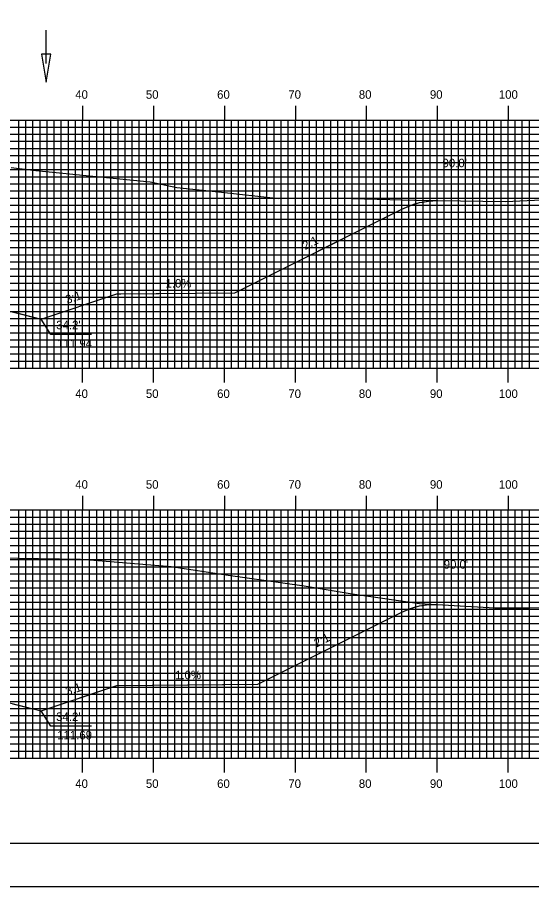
# Model space of a CAD drawing. Extents: x 1768087 to 1768430, y 442591 to 442811.
# Drawn here: x 1768283.8 to 1768356.3, y 442590.5 to 442713.1 of the extents above; entities that cross this region are included whole.
import ezdxf

# ---------------------------------------------------------------- set-up
doc = ezdxf.new("R2010")
doc.units = 0
for name, color, linetype in [('ANNOTATION', 7, 'Continuous'), ('BORDER', 7, 'Continuous'), ('D_Drainage_Ditch_Line', 7, 'Continuous'), ('D_Roadway_Centerline', 7, 'Continuous'), ('D_Roadway_SlopeLines', 7, 'Continuous'), ('D_Text_Standard', 7, 'Continuous'), ('H_V ANNOTATION', 7, 'Continuous'), ('MAJOR', 7, 'Continuous'), ('MINOR', 7, 'Continuous'), ('PLOT BOUNDARY', 7, 'Continuous'), ('S_Roadway_Centerline', 7, 'Continuous')]:
    doc.layers.add(name, color=color, linetype=linetype)

msp = doc.modelspace()

# ---------------------------------------------------------------- linework, layer by layer
at = {"layer": 'ANNOTATION'}
for points in [[(1768294.2, 442668.43), (1768288.51, 442668.43), (1768287.14, 442670.6)], [(1768294.2, 442613.18), (1768288.51, 442613.18), (1768287.14, 442615.35)]]:
    msp.add_lwpolyline(points, dxfattribs=at)
at = {"layer": 'BORDER'}
msp.add_lwpolyline([(1768103.36, 442596.67), (1768423.36, 442596.67), (1768423.36, 442806.67), (1768103.36, 442806.67)], close=True, dxfattribs=at)
at = {"layer": 'D_Drainage_Ditch_Line'}
msp.add_line((1768287.83, 442706.66), (1768287.82, 442711.36), dxfattribs=at)
msp.add_lwpolyline([(1768288.48, 442707.97), (1768287.17, 442707.97), (1768287.83, 442704.03)], close=True, dxfattribs=at)
at = {"layer": 'D_Roadway_Centerline'}
for points in [[(1768283.14, 442671.6), (1768287.14, 442670.6), (1768287.14, 442670.6), (1768297.77, 442674.15), (1768298.34, 442674.15), (1768314.4, 442674.31), (1768314.41, 442674.31), (1768321.65, 442677.93), (1768337.96, 442686.09), (1768338.98, 442686.53), (1768339.21, 442686.63), (1768339.67, 442686.78), (1768340.46, 442687.02), (1768340.87, 442687.09), (1768341.71, 442687.24), (1768342.96, 442687.3)], [(1768283.14, 442616.35), (1768287.13, 442615.35), (1768287.14, 442615.35), (1768291.48, 442616.8), (1768297.77, 442618.9), (1768312.95, 442619.05), (1768317.67, 442619.1), (1768317.67, 442619.1), (1768331.6, 442626.06), (1768337.96, 442629.24), (1768337.96, 442629.24), (1768339.21, 442629.78), (1768339.75, 442629.94), (1768340.46, 442630.14), (1768340.83, 442630.2), (1768341.71, 442630.33), (1768342.96, 442630.35)]]:
    msp.add_lwpolyline(points, dxfattribs=at)
at = {"layer": 'D_Roadway_SlopeLines'}
for points in [[(1768297.77, 442674.15), (1768314.41, 442674.31), (1768337.96, 442686.09), (1768339.21, 442686.63), (1768340.46, 442687.02), (1768341.71, 442687.24), (1768342.96, 442687.3)], [(1768272.96, 442674.15), (1768287.14, 442670.6)], [(1768287.14, 442670.6), (1768297.77, 442674.15)], [(1768297.77, 442618.9), (1768317.67, 442619.1), (1768337.96, 442629.24), (1768339.21, 442629.78), (1768340.46, 442630.14), (1768341.71, 442630.33), (1768342.96, 442630.35)], [(1768272.96, 442618.9), (1768287.14, 442615.35)], [(1768287.14, 442615.35), (1768297.77, 442618.9)]]:
    msp.add_lwpolyline(points, dxfattribs=at)
at = {"layer": 'MAJOR'}
for p, q in [((1768292.96, 442700.67), (1768292.96, 442698.67)), ((1768302.96, 442700.67), (1768302.96, 442698.67)), ((1768312.96, 442700.67), (1768312.96, 442698.67)), ((1768322.96, 442700.67), (1768322.96, 442698.67)), ((1768332.96, 442700.67), (1768332.96, 442698.67)), ((1768342.96, 442700.67), (1768342.96, 442698.67)), ((1768352.96, 442700.67), (1768352.96, 442698.67)), ((1768112.96, 442698.67), (1768392.96, 442698.67)), ((1768112.96, 442698.67), (1768392.96, 442698.67)), ((1768292.96, 442663.67), (1768292.96, 442698.67)), ((1768302.96, 442663.67), (1768302.96, 442698.67)), ((1768312.96, 442663.67), (1768312.96, 442698.67)), ((1768322.96, 442663.67), (1768322.96, 442698.67)), ((1768332.96, 442663.67), (1768332.96, 442698.67)), ((1768342.96, 442663.67), (1768342.96, 442698.67)), ((1768352.96, 442663.67), (1768352.96, 442698.67)), ((1768112.96, 442693.67), (1768392.96, 442693.67)), ((1768112.96, 442688.67), (1768392.96, 442688.67)), ((1768112.96, 442683.67), (1768392.96, 442683.67)), ((1768112.96, 442678.67), (1768392.96, 442678.67)), ((1768112.96, 442673.67), (1768392.96, 442673.67)), ((1768112.96, 442668.67), (1768392.96, 442668.67)), ((1768112.96, 442663.67), (1768392.96, 442663.67)), ((1768112.96, 442663.67), (1768392.96, 442663.67)), ((1768292.96, 442661.66), (1768292.96, 442663.67)), ((1768302.96, 442661.66), (1768302.96, 442663.67)), ((1768312.96, 442661.66), (1768312.96, 442663.67)), ((1768322.96, 442661.66), (1768322.96, 442663.67)), ((1768332.96, 442661.66), (1768332.96, 442663.67)), ((1768342.96, 442661.66), (1768342.96, 442663.67)), ((1768352.96, 442661.66), (1768352.96, 442663.67)), ((1768292.96, 442645.67), (1768292.96, 442643.67)), ((1768302.96, 442645.67), (1768302.96, 442643.67)), ((1768312.96, 442645.67), (1768312.96, 442643.67)), ((1768322.96, 442645.67), (1768322.96, 442643.67)), ((1768332.96, 442645.67), (1768332.96, 442643.67)), ((1768342.96, 442645.67), (1768342.96, 442643.67)), ((1768352.96, 442645.67), (1768352.96, 442643.67)), ((1768112.96, 442643.67), (1768392.96, 442643.67)), ((1768112.96, 442643.67), (1768392.96, 442643.67)), ((1768292.96, 442608.67), (1768292.96, 442643.67)), ((1768302.96, 442608.67), (1768302.96, 442643.67)), ((1768312.96, 442608.67), (1768312.96, 442643.67)), ((1768322.96, 442608.67), (1768322.96, 442643.67)), ((1768332.96, 442608.67), (1768332.96, 442643.67)), ((1768342.96, 442608.67), (1768342.96, 442643.67)), ((1768352.96, 442608.67), (1768352.96, 442643.67)), ((1768112.96, 442638.67), (1768392.96, 442638.67)), ((1768112.96, 442633.67), (1768392.96, 442633.67)), ((1768112.96, 442628.67), (1768392.96, 442628.67)), ((1768112.96, 442623.67), (1768392.96, 442623.67)), ((1768112.96, 442618.67), (1768392.96, 442618.67)), ((1768112.96, 442613.67), (1768392.96, 442613.67)), ((1768112.96, 442608.67), (1768392.96, 442608.67)), ((1768112.96, 442608.67), (1768392.96, 442608.67)), ((1768292.96, 442606.66), (1768292.96, 442608.67)), ((1768302.96, 442606.66), (1768302.96, 442608.67)), ((1768312.96, 442606.66), (1768312.96, 442608.67)), ((1768322.96, 442606.66), (1768322.96, 442608.67)), ((1768332.96, 442606.66), (1768332.96, 442608.67)), ((1768342.96, 442606.66), (1768342.96, 442608.67)), ((1768352.96, 442606.66), (1768352.96, 442608.67))]:
    msp.add_line(p, q, dxfattribs=at)
at = {"layer": 'MINOR'}
for p, q in [((1768283.96, 442663.67), (1768283.96, 442698.67)), ((1768284.96, 442663.67), (1768284.96, 442698.67)), ((1768285.96, 442663.67), (1768285.96, 442698.67)), ((1768286.96, 442663.67), (1768286.96, 442698.67)), ((1768287.96, 442663.67), (1768287.96, 442698.67)), ((1768288.96, 442663.67), (1768288.96, 442698.67)), ((1768289.96, 442663.67), (1768289.96, 442698.67)), ((1768290.96, 442663.67), (1768290.96, 442698.67)), ((1768291.96, 442663.67), (1768291.96, 442698.67)), ((1768293.96, 442663.67), (1768293.96, 442698.67)), ((1768294.96, 442663.67), (1768294.96, 442698.67)), ((1768295.96, 442663.67), (1768295.96, 442698.67)), ((1768296.96, 442663.67), (1768296.96, 442698.67)), ((1768297.96, 442663.67), (1768297.96, 442698.67)), ((1768298.96, 442663.67), (1768298.96, 442698.67)), ((1768299.96, 442663.67), (1768299.96, 442698.67)), ((1768300.96, 442663.67), (1768300.96, 442698.67)), ((1768301.96, 442663.67), (1768301.96, 442698.67)), ((1768303.96, 442663.67), (1768303.96, 442698.67)), ((1768304.96, 442663.67), (1768304.96, 442698.67)), ((1768305.96, 442663.67), (1768305.96, 442698.67)), ((1768306.96, 442663.67), (1768306.96, 442698.67)), ((1768307.96, 442663.67), (1768307.96, 442698.67)), ((1768308.96, 442663.67), (1768308.96, 442698.67)), ((1768309.96, 442663.67), (1768309.96, 442698.67)), ((1768310.96, 442663.67), (1768310.96, 442698.67)), ((1768311.96, 442663.67), (1768311.96, 442698.67)), ((1768313.96, 442663.67), (1768313.96, 442698.67)), ((1768314.96, 442663.67), (1768314.96, 442698.67)), ((1768315.96, 442663.67), (1768315.96, 442698.67)), ((1768316.96, 442663.67), (1768316.96, 442698.67)), ((1768317.96, 442663.67), (1768317.96, 442698.67)), ((1768318.96, 442663.67), (1768318.96, 442698.67)), ((1768319.96, 442663.67), (1768319.96, 442698.67)), ((1768320.96, 442663.67), (1768320.96, 442698.67)), ((1768321.96, 442663.67), (1768321.96, 442698.67)), ((1768323.96, 442663.67), (1768323.96, 442698.67)), ((1768324.96, 442663.67), (1768324.96, 442698.67)), ((1768325.96, 442663.67), (1768325.96, 442698.67)), ((1768326.96, 442663.67), (1768326.96, 442698.67)), ((1768327.96, 442663.67), (1768327.96, 442698.67)), ((1768328.96, 442663.67), (1768328.96, 442698.67)), ((1768329.96, 442663.67), (1768329.96, 442698.67)), ((1768330.96, 442663.67), (1768330.96, 442698.67)), ((1768331.96, 442663.67), (1768331.96, 442698.67)), ((1768333.96, 442663.67), (1768333.96, 442698.67)), ((1768334.96, 442663.67), (1768334.96, 442698.67)), ((1768335.96, 442663.67), (1768335.96, 442698.67)), ((1768336.96, 442663.67), (1768336.96, 442698.67)), ((1768337.96, 442663.67), (1768337.96, 442698.67)), ((1768338.96, 442663.67), (1768338.96, 442698.67)), ((1768339.96, 442663.67), (1768339.96, 442698.67)), ((1768340.96, 442663.67), (1768340.96, 442698.67)), ((1768341.96, 442663.67), (1768341.96, 442698.67)), ((1768343.96, 442663.67), (1768343.96, 442698.67)), ((1768344.96, 442663.67), (1768344.96, 442698.67)), ((1768345.96, 442663.67), (1768345.96, 442698.67)), ((1768346.96, 442663.67), (1768346.96, 442698.67)), ((1768347.96, 442663.67), (1768347.96, 442698.67)), ((1768348.96, 442663.67), (1768348.96, 442698.67)), ((1768349.96, 442663.67), (1768349.96, 442698.67)), ((1768350.96, 442663.67), (1768350.96, 442698.67)), ((1768351.96, 442663.67), (1768351.96, 442698.67)), ((1768353.96, 442663.67), (1768353.96, 442698.67)), ((1768354.96, 442663.67), (1768354.96, 442698.67)), ((1768355.96, 442663.67), (1768355.96, 442698.67)), ((1768112.96, 442697.67), (1768392.96, 442697.67)), ((1768112.96, 442696.67), (1768392.96, 442696.67)), ((1768112.96, 442695.67), (1768392.96, 442695.67)), ((1768112.96, 442694.67), (1768392.96, 442694.67)), ((1768112.96, 442692.67), (1768392.96, 442692.67)), ((1768112.96, 442691.67), (1768392.96, 442691.67)), ((1768112.96, 442690.67), (1768392.96, 442690.67)), ((1768112.96, 442689.67), (1768392.96, 442689.67)), ((1768112.96, 442687.67), (1768392.96, 442687.67)), ((1768112.96, 442686.67), (1768392.96, 442686.67)), ((1768112.96, 442685.67), (1768392.96, 442685.67)), ((1768112.96, 442684.67), (1768392.96, 442684.67)), ((1768112.96, 442682.67), (1768392.96, 442682.67)), ((1768112.96, 442681.67), (1768392.96, 442681.67)), ((1768112.96, 442680.67), (1768392.96, 442680.67)), ((1768112.96, 442679.67), (1768392.96, 442679.67)), ((1768112.96, 442677.67), (1768392.96, 442677.67)), ((1768112.96, 442676.67), (1768392.96, 442676.67)), ((1768112.96, 442675.67), (1768392.96, 442675.67)), ((1768112.96, 442674.67), (1768392.96, 442674.67)), ((1768112.96, 442672.67), (1768392.96, 442672.67)), ((1768112.96, 442671.67), (1768392.96, 442671.67)), ((1768112.96, 442670.67), (1768392.96, 442670.67)), ((1768112.96, 442669.67), (1768392.96, 442669.67)), ((1768112.96, 442667.67), (1768392.96, 442667.67)), ((1768112.96, 442666.67), (1768392.96, 442666.67)), ((1768112.96, 442665.67), (1768392.96, 442665.67)), ((1768112.96, 442664.67), (1768392.96, 442664.67)), ((1768283.96, 442608.67), (1768283.96, 442643.67)), ((1768284.96, 442608.67), (1768284.96, 442643.67)), ((1768285.96, 442608.67), (1768285.96, 442643.67)), ((1768286.96, 442608.67), (1768286.96, 442643.67)), ((1768287.96, 442608.67), (1768287.96, 442643.67)), ((1768288.96, 442608.67), (1768288.96, 442643.67)), ((1768289.96, 442608.67), (1768289.96, 442643.67)), ((1768290.96, 442608.67), (1768290.96, 442643.67)), ((1768291.96, 442608.67), (1768291.96, 442643.67)), ((1768293.96, 442608.67), (1768293.96, 442643.67)), ((1768294.96, 442608.67), (1768294.96, 442643.67)), ((1768295.96, 442608.67), (1768295.96, 442643.67)), ((1768296.96, 442608.67), (1768296.96, 442643.67)), ((1768297.96, 442608.67), (1768297.96, 442643.67)), ((1768298.96, 442608.67), (1768298.96, 442643.67)), ((1768299.96, 442608.67), (1768299.96, 442643.67)), ((1768300.96, 442608.67), (1768300.96, 442643.67)), ((1768301.96, 442608.67), (1768301.96, 442643.67)), ((1768303.96, 442608.67), (1768303.96, 442643.67)), ((1768304.96, 442608.67), (1768304.96, 442643.67)), ((1768305.96, 442608.67), (1768305.96, 442643.67)), ((1768306.96, 442608.67), (1768306.96, 442643.67)), ((1768307.96, 442608.67), (1768307.96, 442643.67)), ((1768308.96, 442608.67), (1768308.96, 442643.67)), ((1768309.96, 442608.67), (1768309.96, 442643.67)), ((1768310.96, 442608.67), (1768310.96, 442643.67)), ((1768311.96, 442608.67), (1768311.96, 442643.67)), ((1768313.96, 442608.67), (1768313.96, 442643.67)), ((1768314.96, 442608.67), (1768314.96, 442643.67)), ((1768315.96, 442608.67), (1768315.96, 442643.67)), ((1768316.96, 442608.67), (1768316.96, 442643.67)), ((1768317.96, 442608.67), (1768317.96, 442643.67)), ((1768318.96, 442608.67), (1768318.96, 442643.67)), ((1768319.96, 442608.67), (1768319.96, 442643.67)), ((1768320.96, 442608.67), (1768320.96, 442643.67)), ((1768321.96, 442608.67), (1768321.96, 442643.67)), ((1768323.96, 442608.67), (1768323.96, 442643.67)), ((1768324.96, 442608.67), (1768324.96, 442643.67)), ((1768325.96, 442608.67), (1768325.96, 442643.67)), ((1768326.96, 442608.67), (1768326.96, 442643.67)), ((1768327.96, 442608.67), (1768327.96, 442643.67)), ((1768328.96, 442608.67), (1768328.96, 442643.67)), ((1768329.96, 442608.67), (1768329.96, 442643.67)), ((1768330.96, 442608.67), (1768330.96, 442643.67)), ((1768331.96, 442608.67), (1768331.96, 442643.67)), ((1768333.96, 442608.67), (1768333.96, 442643.67)), ((1768334.96, 442608.67), (1768334.96, 442643.67)), ((1768335.96, 442608.67), (1768335.96, 442643.67)), ((1768336.96, 442608.67), (1768336.96, 442643.67)), ((1768337.96, 442608.67), (1768337.96, 442643.67)), ((1768338.96, 442608.67), (1768338.96, 442643.67)), ((1768339.96, 442608.67), (1768339.96, 442643.67)), ((1768340.96, 442608.67), (1768340.96, 442643.67)), ((1768341.96, 442608.67), (1768341.96, 442643.67)), ((1768343.96, 442608.67), (1768343.96, 442643.67)), ((1768344.96, 442608.67), (1768344.96, 442643.67)), ((1768345.96, 442608.67), (1768345.96, 442643.67)), ((1768346.96, 442608.67), (1768346.96, 442643.67)), ((1768347.96, 442608.67), (1768347.96, 442643.67)), ((1768348.96, 442608.67), (1768348.96, 442643.67)), ((1768349.96, 442608.67), (1768349.96, 442643.67)), ((1768350.96, 442608.67), (1768350.96, 442643.67)), ((1768351.96, 442608.67), (1768351.96, 442643.67)), ((1768353.96, 442608.67), (1768353.96, 442643.67)), ((1768354.96, 442608.67), (1768354.96, 442643.67)), ((1768355.96, 442608.67), (1768355.96, 442643.67)), ((1768112.96, 442642.67), (1768392.96, 442642.67)), ((1768112.96, 442641.67), (1768392.96, 442641.67)), ((1768112.96, 442640.67), (1768392.96, 442640.67)), ((1768112.96, 442639.67), (1768392.96, 442639.67)), ((1768112.96, 442637.67), (1768392.96, 442637.67)), ((1768112.96, 442636.67), (1768392.96, 442636.67)), ((1768112.96, 442635.67), (1768392.96, 442635.67)), ((1768112.96, 442634.67), (1768392.96, 442634.67)), ((1768112.96, 442632.67), (1768392.96, 442632.67)), ((1768112.96, 442631.67), (1768392.96, 442631.67)), ((1768112.96, 442630.67), (1768392.96, 442630.67)), ((1768112.96, 442629.67), (1768392.96, 442629.67)), ((1768112.96, 442627.67), (1768392.96, 442627.67)), ((1768112.96, 442626.67), (1768392.96, 442626.67)), ((1768112.96, 442625.67), (1768392.96, 442625.67)), ((1768112.96, 442624.67), (1768392.96, 442624.67)), ((1768112.96, 442622.67), (1768392.96, 442622.67)), ((1768112.96, 442621.67), (1768392.96, 442621.67)), ((1768112.96, 442620.67), (1768392.96, 442620.67)), ((1768112.96, 442619.67), (1768392.96, 442619.67)), ((1768112.96, 442617.67), (1768392.96, 442617.67)), ((1768112.96, 442616.67), (1768392.96, 442616.67)), ((1768112.96, 442615.67), (1768392.96, 442615.67)), ((1768112.96, 442614.67), (1768392.96, 442614.67)), ((1768112.96, 442612.67), (1768392.96, 442612.67)), ((1768112.96, 442611.67), (1768392.96, 442611.67)), ((1768112.96, 442610.67), (1768392.96, 442610.67)), ((1768112.96, 442609.67), (1768392.96, 442609.67))]:
    msp.add_line(p, q, dxfattribs=at)
at = {"layer": 'PLOT BOUNDARY'}
msp.add_lwpolyline([(1768087.18, 442590.55), (1768427.18, 442590.55), (1768427.18, 442810.55), (1768087.18, 442810.55)], close=True, dxfattribs=at)
at = {"layer": 'S_Roadway_Centerline'}
for points in [[(1768282.89, 442691.98), (1768286.37, 442691.56), (1768302.48, 442689.93), (1768306.27, 442689.13), (1768312.14, 442688.53), (1768320.63, 442687.59), (1768329.2, 442687.64), (1768339.81, 442687.35), (1768343.04, 442687.3), (1768352.58, 442687.2), (1768358.72, 442687.45), (1768364.56, 442687.62), (1768374.74, 442688.6), (1768378.21, 442688.85), (1768383.6, 442688.96), (1768392.96, 442689.16)], [(1768269.05, 442637.11), (1768292.69, 442636.71), (1768293.14, 442636.7), (1768293.42, 442636.69), (1768305.45, 442635.69), (1768313.49, 442634.47), (1768324.22, 442632.98), (1768330.96, 442631.85), (1768340.46, 442630.49), (1768351.07, 442629.88), (1768352.98, 442629.85), (1768356.04, 442629.88), (1768369.7, 442629.91), (1768375.96, 442630.07), (1768387.64, 442630.81), (1768388.44, 442630.87), (1768390.75, 442630.86), (1768392.96, 442630.87)]]:
    msp.add_lwpolyline(points, dxfattribs=at)

# ---------------------------------------------------------------- texts
at = {"layer": 'ANNOTATION'}
for s, rotation, p in [('2:1', 26.5661, (1768324.33, 442680.31)), ('1.0%', 0.5715, (1768304.66, 442675.02)), ('3:1', 18.4378, (1768290.79, 442672.73)), ('2:1', 26.5641, (1768325.96, 442624.28)), ('1.0%', 0.573, (1768306.01, 442619.78)), ('3:1', 18.4364, (1768290.79, 442617.48))]:
    msp.add_text(s, height=1.2, rotation=rotation, dxfattribs=at).set_placement(p)
for s, p in [("34.2'", (1768289.25, 442669.16)), ('111.94', (1768289.38, 442666.56)), ("34.2'", (1768289.24, 442613.91)), ('111.69', (1768289.38, 442611.31))]:
    msp.add_text(s, height=1.2, dxfattribs=at).set_placement(p)
at = {"layer": 'D_Text_Standard'}
for p in [(1768343.71, 442692.01), (1768343.88, 442635.39)]:
    msp.add_text("90.0'", height=1.2, dxfattribs=at).set_placement(p)
at = {"layer": 'H_V ANNOTATION'}
for s, p in [('40', (1768291.93, 442701.67)), ('50', (1768301.89, 442701.67)), ('60', (1768311.93, 442701.67)), ('70', (1768321.97, 442701.67)), ('80', (1768331.91, 442701.67)), ('90', (1768341.93, 442701.67)), ('100', (1768351.65, 442701.67)), ('40', (1768291.93, 442659.47)), ('50', (1768301.89, 442659.47)), ('60', (1768311.93, 442659.47)), ('70', (1768321.97, 442659.47)), ('80', (1768331.91, 442659.47)), ('90', (1768341.93, 442659.47)), ('100', (1768351.65, 442659.47)), ('40', (1768291.93, 442646.67)), ('50', (1768301.89, 442646.67)), ('60', (1768311.93, 442646.67)), ('70', (1768321.97, 442646.67)), ('80', (1768331.91, 442646.67)), ('90', (1768341.93, 442646.67)), ('100', (1768351.65, 442646.67)), ('40', (1768291.93, 442604.47)), ('50', (1768301.89, 442604.47)), ('60', (1768311.93, 442604.47)), ('70', (1768321.97, 442604.47)), ('80', (1768331.91, 442604.47)), ('90', (1768341.93, 442604.47)), ('100', (1768351.65, 442604.47))]:
    msp.add_text(s, height=1.2, dxfattribs=at).set_placement(p)

doc.saveas('drawing.dxf')
